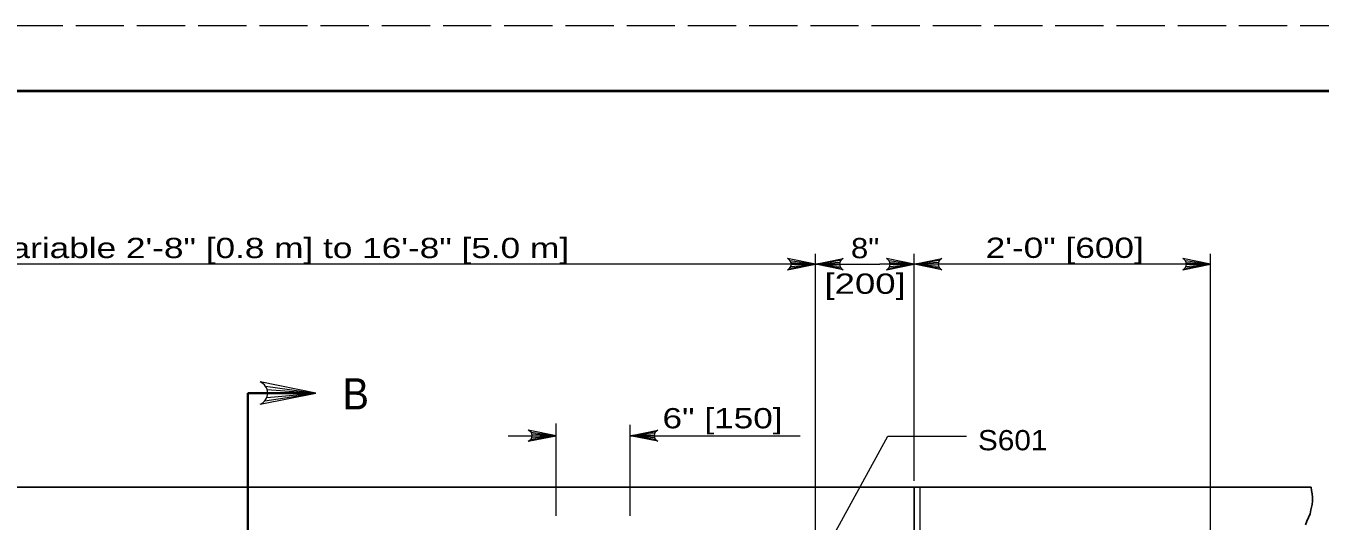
# Model space of a CAD drawing. Extents: x 339.1 to 373.1, y 1412.7 to 1456.7.
# Drawn here: x 351.06 to 361.04, y 1452.93 to 1456.75 of the extents above; entities that cross this region are included whole.
import ezdxf
from ezdxf.enums import TextEntityAlignment as Align

# ---------------------------------------------------------------- set-up
doc = ezdxf.new("R2010")
doc.units = 0
doc.header["$LTSCALE"] = 0.062
doc.linetypes.add('LONG_DASHED', pattern=[7.5, 6, -1.5])
doc.layers.add('1', color=7, linetype='Continuous', lineweight=13)

msp = doc.modelspace()

# ---------------------------------------------------------------- linework, layer by layer
at = {"layer": '1', "lineweight": 25}
for p, q in [((341.0605, 1456.2455), (372.5605, 1456.2455)), ((357.91233, 1453.1925), (360.97275, 1453.1925))]:
    msp.add_line(p, q, dxfattribs=at)
at = {"layer": '1'}
for p, q in [((356.957, 1454.938), (357.15083, 1454.91083)), ((356.9635, 1454.92458), (357.15083, 1454.91083)), ((357.15083, 1452.67717), (357.15083, 1454.9895)), ((357.34475, 1454.938), (357.15083, 1454.91083)), ((357.33817, 1454.92458), (357.15083, 1454.91083)), ((357.71842, 1454.938), (357.91233, 1454.91083)), ((357.725, 1454.92458), (357.91233, 1454.91083)), ((357.91233, 1453.2425), (357.91233, 1454.9895)), ((358.10625, 1454.938), (357.91233, 1454.91083)), ((358.09967, 1454.92458), (357.91233, 1454.91083)), ((360.00292, 1454.938), (360.19683, 1454.91083)), ((360.0095, 1454.92458), (360.19683, 1454.91083)), ((360.19683, 1451.46717), (360.19683, 1454.9895)), ((357.15083, 1454.91083), (355.63825, 1454.91083)), ((356.95467, 1454.88092), (357.15083, 1454.91083)), ((356.96208, 1454.89342), (357.15083, 1454.91083)), ((356.9655, 1454.91083), (357.15083, 1454.91083)), ((357.15083, 1454.91083), (357.64783, 1454.91083)), ((357.33617, 1454.91083), (357.15083, 1454.91083)), ((357.33958, 1454.89342), (357.15083, 1454.91083)), ((357.347, 1454.88092), (357.15083, 1454.91083)), ((357.71617, 1454.88092), (357.91233, 1454.91083)), ((357.72358, 1454.89342), (357.91233, 1454.91083)), ((357.727, 1454.91083), (357.91233, 1454.91083)), ((358.09767, 1454.91083), (357.91233, 1454.91083)), ((358.10108, 1454.89342), (357.91233, 1454.91083)), ((358.1085, 1454.88092), (357.91233, 1454.91083)), ((360.19683, 1454.91083), (359.32017, 1454.91083)), ((360.00067, 1454.88092), (360.19683, 1454.91083)), ((360.00808, 1454.89342), (360.19683, 1454.91083)), ((360.0115, 1454.91083), (360.19683, 1454.91083)), ((352.91067, 1453.972), (353.2985, 1453.91775)), ((352.92383, 1453.94517), (353.2985, 1453.91775)), ((352.90608, 1453.85775), (353.2985, 1453.91775)), ((352.92092, 1453.88292), (353.2985, 1453.91775)), ((352.92783, 1453.91775), (353.2985, 1453.91775)), ((355.15192, 1452.97342), (355.15192, 1453.6845)), ((355.72308, 1452.97342), (355.72308, 1453.67267)), ((354.78367, 1453.58958), (355.15192, 1453.58958)), ((354.95575, 1453.55958), (355.15192, 1453.58958)), ((354.958, 1453.61675), (355.15192, 1453.58958)), ((354.96317, 1453.57217), (355.15192, 1453.58958)), ((354.96458, 1453.60333), (355.15192, 1453.58958)), ((354.96658, 1453.58958), (355.15192, 1453.58958)), ((355.91692, 1453.61675), (355.72308, 1453.58958)), ((355.91042, 1453.60333), (355.72308, 1453.58958)), ((355.72308, 1453.58958), (357.0325, 1453.58958)), ((355.90842, 1453.58958), (355.72308, 1453.58958)), ((355.91183, 1453.57217), (355.72308, 1453.58958)), ((355.91925, 1453.55958), (355.72308, 1453.58958)), ((357.95992, 1452.18633), (357.95992, 1453.1925))]:
    msp.add_line(p, q, dxfattribs=at)
at = {"layer": '1', "lineweight": 35}
for q in [(353.20958, 1453.91775), (352.77492, 1448.08317)]:
    msp.add_line((352.77492, 1453.91775), q, dxfattribs=at)
at = {"layer": '1', "linetype": 'LONG_DASHED'}
msp.add_lwpolyline([(339.0605, 1434.7455), (373.0605, 1434.7455), (373.0605, 1456.7455), (339.0605, 1456.7455)], close=True, dxfattribs=at)
at = {"layer": '1', "lineweight": 40}
msp.add_lwpolyline([(341.0605, 1456.2455), (372.5605, 1456.2455), (372.5605, 1435.2455), (341.0605, 1435.2455)], close=True, dxfattribs=at)
at = {"layer": '1'}
for points in [[(356.93667, 1454.868), (357.15083, 1454.91083), (356.93667, 1454.95367)], [(357.365, 1454.868), (357.15083, 1454.91083), (357.365, 1454.95367)], [(357.69817, 1454.868), (357.91233, 1454.91083), (357.69817, 1454.95367)], [(358.1265, 1454.868), (357.91233, 1454.91083), (358.1265, 1454.95367)], [(359.98267, 1454.868), (360.19683, 1454.91083), (359.98267, 1454.95367)], [(355.63825, 1454.91083), (349.63108, 1454.91083), (349.01208, 1454.91083)], [(359.32017, 1454.91083), (357.91233, 1454.91083), (357.64783, 1454.91083)], [(352.87008, 1453.83208), (353.2985, 1453.91775), (352.87008, 1454.00342)], [(354.93775, 1453.54675), (355.15192, 1453.58958), (354.93775, 1453.63242)], [(355.93725, 1453.54675), (355.72308, 1453.58958), (355.93725, 1453.63242)], [(357.219, 1452.68867), (357.70825, 1453.58567), (358.31458, 1453.58567)]]:
    msp.add_lwpolyline(points, dxfattribs=at)
at = {"layer": '1', "lineweight": 25}
for points in [[(357.91233, 1449.51425), (357.91233, 1453.1925), (343.58617, 1453.1925)], [(360.97275, 1453.1925), (360.97542, 1453.16625), (360.98042, 1453.14067), (360.983, 1453.11242), (360.98425, 1453.0855), (360.98175, 1453.06), (360.97033, 1453.01833), (360.964, 1452.98867), (360.95125, 1452.9605), (360.93858, 1452.93225), (360.92958, 1452.904)]]:
    msp.add_lwpolyline(points, dxfattribs=at)
at = {"layer": '1'}
for centre, radius, start, end in [((356.91939, 1454.91092), 0.04623, 292.08605, 67.91218), ((357.38232, 1454.91092), 0.04623, 112.08782, 247.91395), ((357.68088, 1454.91092), 0.04623, 292.08605, 67.91218), ((358.14381, 1454.91092), 0.04623, 112.08782, 247.91395), ((359.96536, 1454.91092), 0.04623, 292.08605, 67.91218), ((352.83553, 1453.91781), 0.09245, 292.08605, 67.91218), ((354.92047, 1453.58966), 0.04623, 292.08605, 67.91218), ((355.95452, 1453.58966), 0.04623, 112.08782, 247.91395)]:
    msp.add_arc(centre, radius, start, end, dxfattribs=at)

# ---------------------------------------------------------------- texts
for s, height, width, p in [('Variable 2\'-8" [0.8 m] to 16\'-8" [5.0 m]', 0.156, 1.3, (350.76533, 1454.95733)), ('B', 0.24, 0.95, (353.50592, 1453.792)), ('6" [150]', 0.156, 1.3, (355.97233, 1453.64617)), ('S601', 0.156, 1.1, (358.40392, 1453.47708))]:
    msp.add_text(s, height=height, dxfattribs=dict(at, width=width)).set_placement(p)
for s, width, p in [('2\'-0" [600]', 1.3, (359.07304, 1454.95867)), ('8"', 1.15, (357.53429, 1454.95625)), ('[200]', 1.35, (357.53437, 1454.68225))]:
    msp.add_text(s, height=0.156, dxfattribs=dict(at, width=width)).set_placement(p, align=Align.CENTER)

doc.saveas('drawing.dxf')
